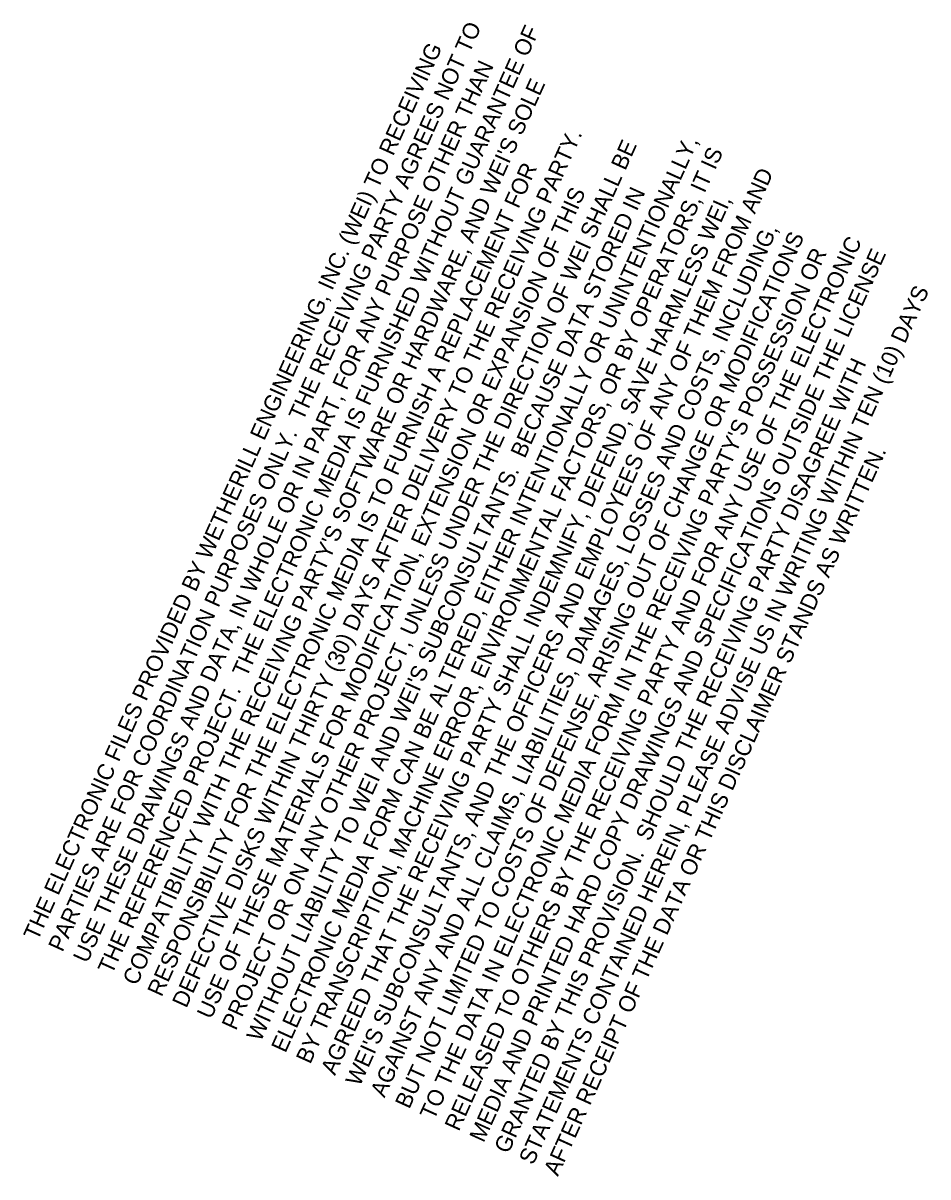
# Model space of a CAD drawing. Extents: x 1744741 to 2014229, y 466994 to 951338.
# Drawn here: x 2012338 to 2014229, y 481667 to 484079 of the extents above; entities that cross this region are included whole.
import ezdxf

# ---------------------------------------------------------------- set-up
doc = ezdxf.new("R2010")
doc.units = 0
doc.layers.add('Default', color=7, linetype='Continuous')

msp = doc.modelspace()

# ---------------------------------------------------------------- texts
at = {"layer": 'Default'}
for s, p in [('PARTIES ARE FOR COORDINATION PURPOSES ONLY.  THE RECEIVING PARTY AGREES NOT TO ', (2012420.1, 482135.4)), ('THE REFERENCED PROJECT.  THE ELECTRONIC MEDIA IS FURNISHED WITHOUT GUARANTEE OF ', (2012523.7, 482088.5)), ('THE ELECTRONIC FILES PROVIDED BY WETHERILL ENGINEERING, INC. (WEI) TO RECEIVING ', (2012368.4, 482158.9)), ('USE THESE DRAWINGS AND DATA, IN WHOLE OR IN PART, FOR ANY PURPOSE OTHER THAN ', (2012471.9, 482112)), ("COMPATIBILITY WITH THE RECEIVING PARTY'S SOFTWARE OR HARDWARE, AND WEI'S SOLE ", (2012575.5, 482065.1)), ('DEFECTIVE DISKS WITHIN THIRTY (30) DAYS AFTER DELIVERY TO THE RECEIVING PARTY.  ', (2012679, 482018.2)), ('PROJECT OR ON ANY OTHER PROJECT, UNLESS UNDER THE DIRECTION OF WEI SHALL BE ', (2012782.6, 481971.4)), ('ELECTRONIC MEDIA FORM CAN BE ALTERED, EITHER INTENTIONALLY OR UNINTENTIONALLY, ', (2012886.1, 481924.5)), ('BY TRANSCRIPTION, MACHINE ERROR, ENVIRONMENTAL FACTORS, OR BY OPERATORS, IT IS ', (2012937.9, 481901.1)), ('RESPONSIBILITY FOR THE ELECTRONIC MEDIA IS TO FURNISH A REPLACEMENT FOR ', (2012627.2, 482041.7)), ("WEI'S SUBCONSULTANTS, AND THE OFFICERS AND EMPLOYEES OF ANY OF THEM FROM AND ", (2013041.5, 481854.2)), ("WITHOUT LIABILITY TO WEI AND WEI'S SUBCONSULTANTS.  BECAUSE DATA STORED IN ", (2012834.4, 481947.9)), ('USE OF THESE MATERIALS FOR MODIFICATION, EXTENSION OR EXPANSION OF THIS ', (2012730.8, 481994.8)), ('AGREED THAT THE RECEIVING PARTY SHALL INDEMNIFY, DEFEND, SAVE HARMLESS WEI, ', (2012989.7, 481877.6)), ('AGAINST ANY AND ALL CLAIMS, LIABILITIES, DAMAGES, LOSSES AND COSTS, INCLUDING, ', (2013093.2, 481830.8)), ('BUT NOT LIMITED TO COSTS OF DEFENSE, ARISING OUT OF CHANGE OR MODIFICATIONS ', (2013145, 481807.3)), ('RELEASED TO OTHERS BY THE RECEIVING PARTY AND FOR ANY USE OF THE ELECTRONIC ', (2013248.6, 481760.5)), ("TO THE DATA IN ELECTRONIC MEDIA FORM IN THE RECEIVING PARTY'S POSSESSION OR ", (2013196.8, 481783.9)), ('MEDIA AND PRINTED HARD COPY DRAWINGS AND SPECIFICATIONS OUTSIDE THE LICENSE ', (2013300.3, 481737)), ('STATEMENTS CONTAINED HEREIN, PLEASE ADVISE US IN WRITING WITHIN TEN (10) DAYS ', (2013403.9, 481690.1)), ('GRANTED BY THIS PROVISION.  SHOULD THE RECEIVING PARTY DISAGREE WITH ', (2013352.1, 481713.6)), ('AFTER RECEIPT OF THE DATA OR THIS DISCLAIMER STANDS AS WRITTEN.', (2013455.7, 481666.7))]:
    msp.add_text(s, height=34.099, rotation=65.6469, dxfattribs=at).set_placement(p)

doc.saveas('drawing.dxf')
